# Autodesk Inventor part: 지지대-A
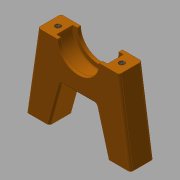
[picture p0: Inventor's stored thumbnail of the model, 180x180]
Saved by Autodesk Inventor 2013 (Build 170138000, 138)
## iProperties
Created: 2018-01
Part Number: 지지대-A
Material: 일반
Document SubType Name: Modeling
Designer: mduedu
Density: 1 g/cm^3
Mass: 8.09801 g
Surface Area: 38.5771 cm^2
Volume: 8.09801 cm^3
Author: mduedu
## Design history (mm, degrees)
sketch "스케치1"
  geometry: L1 (-22.5, 0)-(22.5, 0); L2 (22.5, 0)-(17.5, 34); L3 (17.5, 34)-(-17.5, 34); L4 (-17.5, 34)-(-22.5, 0); 3 further points
  constraints: 8 end point, 2 midpoint, 1 coincident, 1 horizontal, 1 parallel, 1 vertical alignment
  dimensions: "d0" = 45 distance of L1.start L1.end; "d3" = 35 distance of L2.end L3.end; "d4" = 34 vertical distance of L1.end L2.end
extrude "돌출1" new body sketch "스케치1" stored distance "d5" = 10; taper "d6" = 0 deg
sketch "스케치2"
  geometry: L1 (-12.5, 0)-(12.5, 0); L2 (12.5, 0)-(7.5, 18); L3 (7.5, 18)-(-7.5, 18); L4 (-7.5, 18)-(-12.5, 0); L5 (-22.5, 0)-(22.5, 0) reference; 4 further points
  constraints: 8 end point, 4 midpoint, 1 horizontal, 1 parallel, 1 vertical alignment
  dimensions: "d7" = 10 distance of L1.start L5.start; "d8" = 10 distance of L1.end L5.end (derived); "d9" = 15 distance of L2.end L3.end; "d10" = 18 distance between parallel lines of L1 L3
extrude "돌출2" cut sketch "스케치2" stored distance "d11" = 10; taper "d12" = 0 deg
sketch "스케치3"
  geometry: L1 (-17.5, 34)-(17.5, 34) reference; C1 r 11 at (0, 34); C2 r 9 at (0, 34); 1 further point
  constraints: 2 centre point, 1 coincident, 1 midpoint
  dimensions: "d13" = 22 diameter of C1; "d16" = 18 diameter of C2
extrude "돌출3" cut sketch "스케치3" stored distance "d14" = 7; taper "d15" = 0 deg
extrude "돌출4" cut sketch "스케치3" stored distance "d17" = 7; taper "d18" = 0 deg
fillet "모깎기1" dims "d19" = 0.3
fillet "모깎기2" dims "d20" = 1
fillet "모깎기3" dims "d21" = 1
fillet "모깎기4" dims "d22" = 1
sketch "스케치4"
  geometry: 2 further points
  constraints: 2 other
hole "구멍1" sketch "스케치4" at (-22.771, -3.5), (4.771, -3.5) diameter "d23" = 2.459; stored, may be unused: countersink angle "d27" = 90 deg, drill point angle "d29" = 120 deg; dims "d24" = 4.5, "d25" = 4, "d26" = 2, "d28" = 6
sketch "스케치5"
  geometry: 4 further points
  constraints: 4 other
hole "구멍2" sketch "스케치5" at (40, 4), (5, -27), (40, -27), (5, 4) diameter "d30" = 2.459; stored, may be unused: countersink angle "d34" = 90 deg, drill point angle "d36" = 120 deg; dims "d31" = 6.9, "d32" = 4, "d33" = 2, "d35" = 8.4
node "솔리드1"
